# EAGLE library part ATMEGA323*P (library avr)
MICROCONTROLLER 32 Kbytes FLASH 2 Kbytes SRAM 1 Kbytes EEPROM USART 8-channel 10 bit ADC
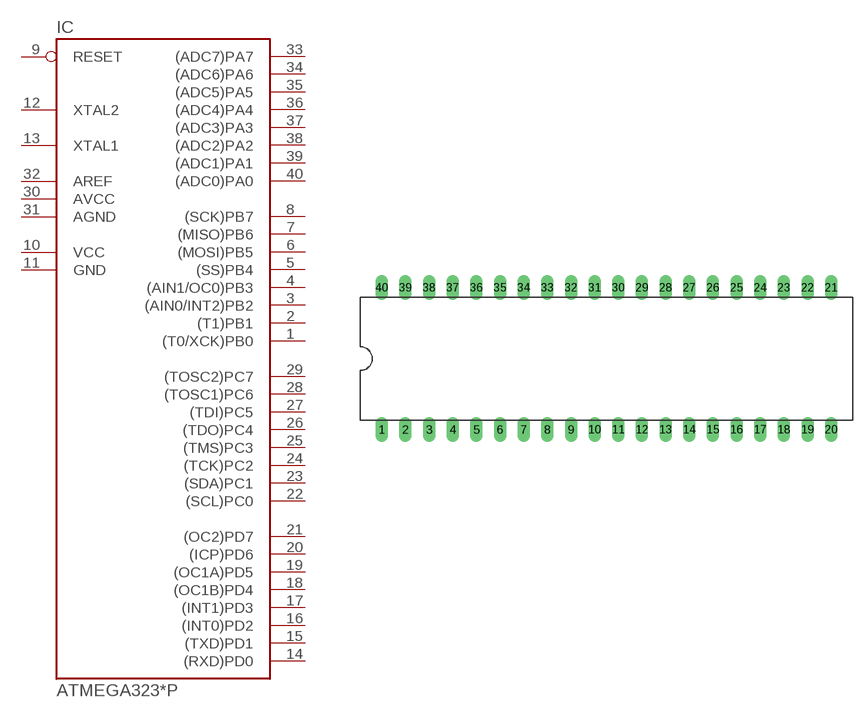
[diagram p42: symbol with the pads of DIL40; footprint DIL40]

Designator prefix IC

## ATMEGA323-8P, ATMEGA323L-4P  [DIL40]
1  (T0/XCK)PB0
2  (T1)PB1
3  (AIN0/INT2)PB2
4  (AIN1/OC0)PB3
5  (SS)PB4
6  (MOSI)PB5
7  (MISO)PB6
8  (SCK)PB7
9  RESET  in
10  VCC  pwr
11  GND  pwr
12  XTAL2
13  XTAL1
14  (RXD)PD0
15  (TXD)PD1
16  (INT0)PD2
17  (INT1)PD3
18  (OC1B)PD4
19  (OC1A)PD5
20  (ICP)PD6
21  (OC2)PD7
22  (SCL)PC0
23  (SDA)PC1
24  (TCK)PC2
25  (TMS)PC3
26  (TDO)PC4
27  (TDI)PC5
28  (TOSC1)PC6
29  (TOSC2)PC7
30  AVCC  pwr
31  AGND  pwr
32  AREF  pwr
33  (ADC7)PA7
34  (ADC6)PA6
35  (ADC5)PA5
36  (ADC4)PA4
37  (ADC3)PA3
38  (ADC2)PA2
39  (ADC1)PA1
40  (ADC0)PA0

## Footprint DIL40 (pad centres in mm)
Dual In Line
drill 0.813 long: 1 -24.13,-7.62; 2 -21.59,-7.62; 3 -19.05,-7.62; 4 -16.51,-7.62; 5 -13.97,-7.62; 6 -11.43,-7.62; 7 -8.89,-7.62; 8 -6.35,-7.62; 9 -3.81,-7.62; 10 -1.27,-7.62; 11 1.27,-7.62; 12 3.81,-7.62; 13 6.35,-7.62; 14 8.89,-7.62; 15 11.43,-7.62; 16 13.97,-7.62; 17 16.51,-7.62; 18 19.05,-7.62; 19 21.59,-7.62; 20 24.13,-7.62; 21 24.13,7.62; 22 21.59,7.62; 23 19.05,7.62; 24 16.51,7.62; 25 13.97,7.62; 26 11.43,7.62; 27 8.89,7.62; 28 6.35,7.62; 29 3.81,7.62; 30 1.27,7.62; 31 -1.27,7.62; 32 -3.81,7.62; 33 -6.35,7.62; 34 -8.89,7.62; 35 -11.43,7.62; 36 -13.97,7.62; 37 -16.51,7.62; 38 -19.05,7.62; 39 -21.59,7.62; 40 -24.13,7.62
